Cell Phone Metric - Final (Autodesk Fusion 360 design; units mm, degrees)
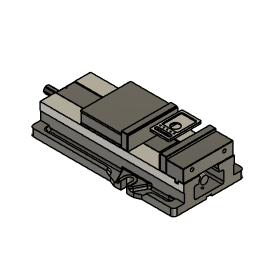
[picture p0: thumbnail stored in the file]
description: HaasClamp
derived_base_feature "Derived Base Feature" bodies "Main Body"
align "Align1"
sketch "Sketch1" plane through (0, 0, 0) normal (0, 0, -1) x axis (1, 0, 0)
  line L1 (30, 46.5) -> (30, -46.5)
  line L2 (-26.5, 50) -> (26.5, 50)
  line L3 (-30, -46.5) -> (-30, 46.5)
  line L4 (26.5, -50) -> (-26.5, -50)
  line L5 (-23.5, 38.5) -> (-23.5, 36)
  line L6 (20, 42) -> (-20, 42)
  line L7 (23.5, 36) -> (23.5, 38.5)
  line L8 (-20, 32.5) -> (20, 32.5)
  line L9 (-50.8, -55) -> (50.8, -55)
  line L10 (-50.8, 55) -> (-50.8, -55)
  line L11 (50.8, 55) -> (-50.8, 55)
  line L12 (50.8, -55) -> (50.8, 55)
  line L13 (-50.8, 55) -> (50.8, -55)
  line L14 (50.8, 55) -> (-50.8, -55)
  arc A1 centre (26.5, -46.5) radius 3.5 clockwise from (30, -46.5) to (26.5, -50)
  arc A2 centre (26.5, 46.5) radius 3.5 clockwise from (26.5, 50) to (30, 46.5)
  arc A3 centre (-26.5, 46.5) radius 3.5 clockwise from (-30, 46.5) to (-26.5, 50)
  arc A4 centre (-26.5, -46.5) radius 3.5 clockwise from (-26.5, -50) to (-30, -46.5)
  circle C1 centre (10.5, 25) radius 2.117
  circle C2 centre (-10.5, 25) radius 2.117
  circle C3 centre (-21, 25) radius 2.117
  circle C4 centre (0, 25) radius 2.117
  circle C5 centre (21, 25) radius 2.117
  arc A5 centre (-20, 38.5) radius 3.5 clockwise from (-23.5, 38.5) to (-20, 42)
  arc A6 centre (20, 38.5) radius 3.5 clockwise from (20, 42) to (23.5, 38.5)
  arc A7 centre (20, 36) radius 3.5 clockwise from (23.5, 36) to (20, 32.5)
  arc A8 centre (-20, 36) radius 3.5 clockwise from (-20, 32.5) to (-23.5, 36)
  circle C6 centre (0, 0) radius 12.5
  point P36 (0, 0)
  point P1 (0, 0)
  point P34 (-50.8, 55)
  point P35 (50.8, 55)
  point P32 (50.8, -55)
  horizontal L9
  perpendicular L9 L10
  parallel L9 L11
  parallel L10 L12
  coincident L13 P36
  coincident L14 P36
  coincident P1 P36
  dimension "d1" distance P34 P35 = 101.6
  dimension "d2" distance P32 P35 = 110
extrude "Extrude1" new body sketch "Sketch1" profile of L9 L10 L11 L12 against normal blind 6 bodies "Stock"
base_feature "Base Feature1"
base_feature "Base Feature1"
base_feature "Base Feature1"
base_feature "Base Feature1"
base_feature "Base Feature1"
base_feature "Base Feature1"
base_feature "Base Feature1"
base_feature "Base Feature1"
base_feature "Base Feature1"
base_feature "Base Feature1"
as_built_joint "As-built1"
as_built_joint "As-built2"
as_built_joint "As-built3"
joint_origin "JointOrigin1" OffsetX 0 OffsetY 0 OffsetZ 0 AngleZ 0
joint "Assemble1" alignAngle 180 alignOffsetX 0 alignOffsetY 0 alignOffsetZ 0 (= "jaw_width_haas_050002") SlideMaximum 22.5 SlideMinimum 0
position "Position1"
sketch "Sketch1" plane through (0, -72.5, 0) normal (0, -1, 0) x axis (1, 0, 0)
  line L1 (75, 73) -> (-75, 73)
  line L2 (76, 74) -> (75, 73)
  line L3 (76, 116.5) -> (76, 74)
  line L4 (75, 117.5) -> (76, 116.5)
  line L5 (-75, 117.5) -> (75, 117.5)
  line L6 (-76, 116.5) -> (-75, 117.5)
  line L7 (-76, 74) -> (-76, 116.5)
  line L8 (-75, 73) -> (-76, 74)
  line L9 (76.4, 114.275) -> (-76, 114.275)
  line L10 (76.4, 73) -> (76.4, 114.275)
  line L11 (-76, 73) -> (76.4, 73)
  line L12 (-76, 114.275) -> (-76, 73)
  circle C1 centre (49.21, 96.8) radius 11
  circle C2 centre (-49.21, 96.8) radius 11
  point P14 (76.4, 73)
  point P12 (-76, 114.275)
  point P13 (76.4, 114.275)
  horizontal L9
  vertical L10
  horizontal L11
  vertical L12
  coincident L1 P14
  coincident L7 P12
  dimension "d16" distance P12 P13 = 152.4
  dimension "d17" distance P13 P14 = 41.275
place_component sketch "Sketch1"
extrude "Extrude1" new body sketch "Sketch1" profile of L1 L2 L3 L7 L8 C1 C2 L9 L11 L12 along normal blind 3.175
place_component sketch "Sketch1"
extrude "Extrude1" sketch "Sketch1" profile of L1 L2 L3 L7 L8 C1 C2 L9 L11 L12 blind -3.175
as_built_joint "As-built5"
as_built_joint "As-built6"
position "Position1"
ground "Pin"
position "Position2"
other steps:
create_component "CreateComponent1"
create_component "CreateComponent2"
create_component "CreateComponent3"
create_component "CreateComponent4"
create_component "CreateComponent5"
create_component "CreateComponent6"
create_component "CreateComponent7"
create_component "CreateComponent8"
create_component "CreateComponent9"
create_component "CreateComponent10"
joint_origin "JointOrigin10"
joint_origin "JointOrigin11"
create_component "CreateComponent11" sketch "Sketch1"
create_component "CreateComponent12" sketch "Sketch1"
create_component "CreateComponent1"
named bodies: "Main Body", "Stock"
